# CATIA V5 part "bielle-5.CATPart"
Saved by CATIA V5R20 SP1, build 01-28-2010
Part number: bielle-5
Bounding box of the stored display mesh (mm): x -1022.474 to 157.527, y -13.57 to 16.43, z 0 to 30
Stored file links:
  C:\Users\Manon\Desktop\IAO\Pieces\bielle-5.CATPart
  C:\Users\Manon\Desktop\IAO\assemblage\Assemblage_rlanglais.CATProduct
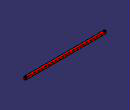
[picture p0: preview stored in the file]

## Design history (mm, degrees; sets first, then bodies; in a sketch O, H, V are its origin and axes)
External parameters (linked from other documents)
  External.bielle_5 = 1140 mm
Body1 (main body)
  Sketch1 on xy-plane, origin (0, 0, 0), H (1, 0, 0), V (0, 1, 0)
    line L1 (-1022.4735, 16.4303) -> (157.5265, 16.4303)
    line L2 (157.5265, 16.4303) -> (157.5265, -13.5697)
    line L3 (157.5265, -13.5697) -> (-1022.4735, -13.5697)
    line L4 (-1022.4735, -13.5697) -> (-1022.4735, 16.4303)
    circle A1 centre (-1002.4735, 1.4303) radius 10
    point P5 (-1002.4735, 1.4303)
    circle A2 centre (137.5265, 1.4303) radius 10
    point P6 (137.5265, 1.4303)
    length L2 = 30
    length L1 = 1180
    radius A2 = 10
    radius A1 = 10
    distance P6 L3 = 15
    distance P5 L3 = 15
    distance P6 P5 = 1140 {= External.bielle_5}
    distance P5 L4 = 20
    horizontal: L1 H, L3 H
    vertical: L2 V, L4 V
  Pad1: profile Sketch1, direction (0, 0, 1), length 30
  Fillet1: radius 5, on edge [face of Pad1 from Sketch1.L1 | face of Pad1 from Sketch1.L2]; edge [face of Pad1 from Sketch1.L2 | face of Pad1 from Sketch1.L3]; edge [face of Pad1 from Sketch1.L3 | face of Pad1 from Sketch1.L4]; edge [face of Pad1 from Sketch1.L4 | face of Pad1 from Sketch1.L1]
